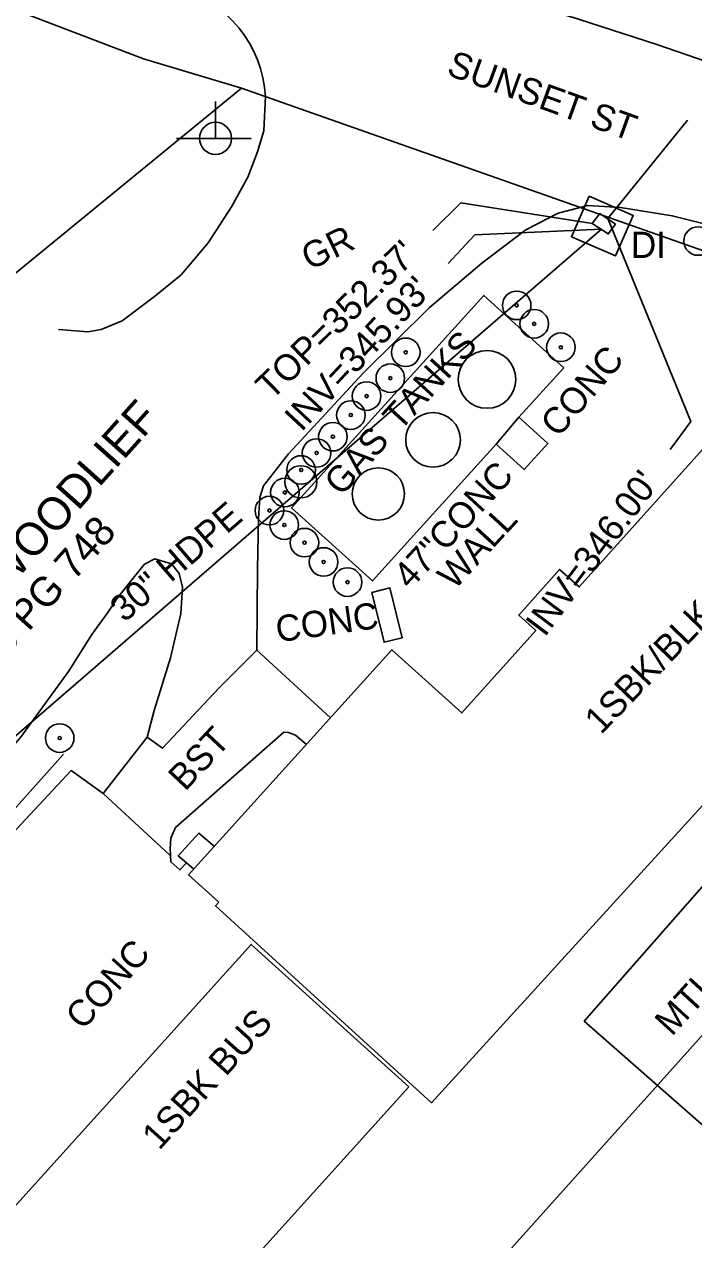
# Model space of a CAD drawing. Extents: x 2089016 to 2094354, y 862840 to 864725.
# Drawn here: x 2091878.1 to 2091980.3, y 864032.6 to 864218.1 of the extents above; entities that cross this region are included whole.
import ezdxf

# ---------------------------------------------------------------- set-up
doc = ezdxf.new("R2010")
doc.units = 0
for name, color, linetype in [('Exist Building', 7, 'Continuous'), ('Exist Building Metal Canopy', 7, 'Continuous'), ('Exist Building Metal Canopy Text', 7, 'Continuous'), ('Exist Building Text', 7, 'Continuous'), ('Exist Other Culture AG Tank', 7, 'Continuous'), ('Exist Other Culture AG Tank Text', 7, 'Continuous'), ('Exist Other Culture Area Outline', 7, 'Continuous'), ('Exist Other Culture Area Outline Text', 7, 'Continuous'), ('Exist Other Culture Fence Line', 7, 'Continuous'), ('Exist Other Culture Located Object CELL', 7, 'Continuous'), ('Exist Property Deed Book Text', 7, 'Continuous'), ('Exist Property Line', 7, 'Continuous'), ('Exist Property Owner Text', 7, 'Continuous'), ('Exist Right of Way Line', 7, 'Continuous'), ('Exist Roads Change in Surface', 7, 'Continuous'), ('Exist Roads EOP', 7, 'Continuous'), ('Exist Roads EOP Other', 7, 'Continuous'), ('Exist Roads EOP Other Text', 7, 'Continuous'), ('Exist Roads EOT', 7, 'Continuous'), ('Exist Roads Soil', 7, 'Continuous'), ('Exist Roads Soil Text', 7, 'Continuous'), ('Exist Structure Minor Drop Inlet', 7, 'Continuous'), ('Exist Structure Minor Drop Inlet Leader', 7, 'Continuous'), ('Exist Structure Minor Drop Inlet Text', 7, 'Continuous'), ('Exist Structure Minor Drop Inlet Top Elevation', 7, 'Continuous'), ('Exist Structure Minor Paved Ditch or Gutter', 7, 'Continuous'), ('Exist Structure Minor Pipes HDPE 30 Inch', 7, 'Continuous'), ('Exist Structure Minor Pipes HDPE 30 Inch Invert', 7, 'Continuous'), ('Exist Structure Minor Pipes HDPE 30 Inch Leader', 7, 'Continuous'), ('Exist Structure Minor Pipes HDPE 30 Inch Text', 7, 'Continuous'), ('Exist Structure Minor Pipes RCP 30 Inch', 7, 'Continuous'), ('Exist Structure Minor Pipes RCP 30 Inch Invert', 7, 'Continuous'), ('Exist Structure Minor Pipes RCP 30 Inch Leader', 7, 'Continuous'), ('Prop Drainage Structure Pipe RCP 30in Class IV Label', 7, 'Continuous'), ('Prop Drainage Structure Pipe RCP 36in Class IV', 7, 'Continuous'), ('Prop SS Fill Line', 7, 'Continuous'), ('R5707_NCDOT_FS_170814 - Exist Roads EOT', 7, 'Continuous')]:
    doc.layers.add(name, color=color, linetype=linetype)

msp = doc.modelspace()

# ---------------------------------------------------------------- linework, layer by layer
at = {"layer": 'Exist Building'}
msp.add_line((2091950.15, 864153.99), (2091953.61, 864158.12), dxfattribs=at)
msp.add_lwpolyline([(2091950.15, 864153.99), (2091931.26, 864133.13), (2091918.93, 864144.3), (2091948.29, 864176.71), (2091960.46, 864165.68), (2091953.61, 864158.12)], dxfattribs=at)
msp.add_lwpolyline([(2092025.57, 864147.09), (2091940.29, 864053.5), (2091907.31, 864083.55), (2091907.81, 864084.1), (2091903.21, 864088.27), (2091934.25, 864122.63), (2091944.9, 864112.99), (2091956.19, 864125.59), (2091953.59, 864127.93), (2091959.84, 864134.9), (2091962.84, 864132.21), (2091997.36, 864170.68), (2091998.21, 864171.63)], close=True, dxfattribs=at)
at = {"layer": 'Exist Building Metal Canopy'}
for points in [[(2092008.24, 864079.99), (2091981.86, 864049.93), (2091963.6, 864065.96), (2091989.97, 864096.01)], [(2091936.84, 864055.9), (2091875.11, 863987.57), (2091851.02, 864009.33), (2091912.76, 864077.66)]]:
    msp.add_lwpolyline(points, close=True, dxfattribs=at)
at = {"layer": 'Exist Other Culture AG Tank'}
for centre, radius in [((2091948.75, 864163.89), 4.41), ((2091940.51, 864154.66), 4.17), ((2091932.17, 864146.41), 3.99)]:
    msp.add_circle(centre, radius, dxfattribs=at)
at = {"layer": 'Exist Other Culture Area Outline'}
for points in [[(2091953.61, 864158.12), (2091958.01, 864154.13), (2091954.4, 864150.14), (2091950.15, 864153.99)], [(2091902.88, 864090.12), (2091901.6, 864091.2), (2091904.79, 864094.66), (2091907.14, 864092.62)]]:
    msp.add_lwpolyline(points, dxfattribs=at)
msp.add_lwpolyline([(2091931.15, 864131.39), (2091933.05, 864123.78), (2091935.82, 864124.47), (2091933.93, 864132.08)], close=True, dxfattribs=at)
at = {"layer": 'Exist Other Culture Fence Line'}
msp.add_line((2091857.39, 864076.87), (2091884.1, 864106.7), dxfattribs=at)
at = {"layer": 'Exist Other Culture Located Object CELL'}
for centre, radius in [((2091953.28, 864175.19), 2.18), ((2091953.28, 864175.19), 0.24), ((2091955.95, 864172.38), 2.18), ((2091955.95, 864172.38), 0.24), ((2091936.35, 864168.03), 2.18), ((2091960.02, 864168.8), 2.18), ((2091936.35, 864168.03), 0.24), ((2091960.02, 864168.8), 0.24), ((2091933.99, 864164.08), 2.18), ((2091933.99, 864164.08), 0.24), ((2091930.37, 864161.34), 2.18), ((2091927.97, 864158.45), 2.18), ((2091930.37, 864161.34), 0.24), ((2091927.97, 864158.45), 0.24), ((2091925.23, 864155.15), 2.18), ((2091922.74, 864152.66), 2.18), ((2091925.23, 864155.15), 0.24), ((2091922.74, 864152.66), 0.24), ((2091920.38, 864150.07), 2.18), ((2091920.38, 864150.07), 0.24), ((2091917.9, 864146.63), 2.18), ((2091915.55, 864143.88), 2.18), ((2091917.9, 864146.63), 0.24), ((2091915.55, 864143.88), 0.24), ((2091917.81, 864141.66), 2.18), ((2091917.81, 864141.66), 0.24), ((2091920.89, 864138.98), 2.18), ((2091920.89, 864138.98), 0.24), ((2091923.81, 864136.03), 2.18), ((2091923.81, 864136.03), 0.24), ((2091927.46, 864132.95), 2.18), ((2091927.46, 864132.95), 0.24), ((2091883.53, 864109.15), 2.18), ((2091883.53, 864109.15), 0.24)]:
    msp.add_circle(centre, radius, dxfattribs=at)
at = {"layer": 'Exist Property Line'}
msp.add_line((2091911.3, 864208.32), (2091739.6, 864068.07), dxfattribs=at)
at = {"layer": 'Exist Right of Way Line'}
for p, q in [((2091768.57, 864261.63), (2091896.32, 864212.8)), ((2091896.32, 864212.8), (2091911.3, 864208.32)), ((2091911.3, 864208.32), (2092063.24, 864154.88)), ((2092063.24, 864154.88), (2091854.39, 863921.86))]:
    msp.add_line(p, q, dxfattribs=at)
at = {"layer": 'Exist Roads Change in Surface'}
msp.add_line((2091890.18, 864100.7), (2091900.32, 864091.3), dxfattribs=at)
at = {"layer": 'Exist Roads EOP'}
msp.add_spline([(2091734.18, 863736.92), (2091737.57, 863740.74), (2091742.7, 863746.41), (2091746.39, 863749.99), (2091752.74, 863757.34), (2091779.15, 863786.15), (2091800.43, 863809.86), (2091817.14, 863828.66), (2091827.31, 863840.06), (2091854.93, 863870.83), (2091881.2, 863900.12), (2091888.17, 863907.69), (2091904.65, 863926.31), (2091929.6, 863954.75), (2091942.38, 863969.24), (2091969.89, 863999.82), (2091984.53, 864016.32), (2091999.97, 864033.43), (2092012.73, 864047.99), (2092025.65, 864062.7), (2092046.42, 864086.24), (2092066.29, 864109.17), (2092073.24, 864116), (2092075.7, 864118.27)], degree=3, dxfattribs=at)
at = {"layer": 'Exist Roads EOP Other'}
for points in [[(2091830.63, 863994.76), (2091827.43, 863997.96), (2091826.47, 864000.61), (2091825.69, 864006.48), (2091825.91, 864011.04), (2091828.35, 864018.06), (2091835.42, 864033.2), (2091847.32, 864055.21), (2091857.99, 864074.56), (2091869.16, 864086.97), (2091885.3, 864104.18), (2091890.18, 864100.7), (2091896.88, 864109.31), (2091899.21, 864107.63), (2091907.87, 864116.83), (2091913.63, 864122.58), (2091924.84, 864112.22)], [(2091921.18, 864108.17), (2091919.53, 864109.62), (2091918.47, 864110.01), (2091917.74, 864110.04), (2091901.22, 864095.48), (2091900.51, 864093.89), (2091900.38, 864092.28), (2091900.51, 864090.26), (2091901.87, 864089.03), (2091902.88, 864090.12), (2091904.01, 864089.16)]]:
    msp.add_lwpolyline(points, dxfattribs=at)
at = {"layer": 'Exist Roads EOT'}
msp.add_spline([(2091640.57, 863633.96), (2091642.21, 863635.11), (2091649.13, 863640.68), (2091667.19, 863659.41), (2091696.8, 863691.67), (2091725.32, 863721.95), (2091736.55, 863733.98), (2091755.7, 863754.61), (2091782.35, 863783.06), (2091806.22, 863808.81), (2091831.4, 863835.96), (2091859.62, 863866.77), (2091886.36, 863896.04), (2091909.82, 863922.03), (2091934.52, 863949.57), (2091947.55, 863964.17), (2091975.11, 863995.05), (2091990.59, 864012.13), (2092005.14, 864028.47), (2092018.17, 864043.09), (2092031.63, 864058.14), (2092052.57, 864081.55), (2092071.9, 864103.07)], degree=3, dxfattribs=at)
at = {"layer": 'Exist Roads Soil'}
msp.add_line((2091897.94, 864113.34), (2091896.88, 864109.31), dxfattribs=at)
for points in [[(2091932.99, 864228.49), (2091950.66, 864222.62), (2091962.74, 864218.85), (2091974.68, 864215.02), (2091986.8, 864210.83), (2091997.29, 864206.81), (2092009.63, 864202.38)], [(2091914.93, 864207.11), (2091914.69, 864201.83), (2091913.71, 864198.61), (2091912.27, 864194.76), (2091909.76, 864190.25), (2091906.21, 864184.74), (2091902.07, 864179.84), (2091897.99, 864176.52), (2091893.08, 864172.84), (2091889.86, 864171.49), (2091887.83, 864171.15), (2091883.35, 864171.53)], [(2091913.63, 864122.58), (2091913.74, 864134.95), (2091913.85, 864142.59), (2091914.08, 864145.89), (2091914.62, 864147.64), (2091918.44, 864152.53), (2091929.87, 864164.85), (2091939.94, 864174.81), (2091947.96, 864181.64), (2091954.7, 864186.73), (2091959.62, 864189.26), (2091964.12, 864190.41), (2091969.13, 864190.14), (2091977.03, 864188.86), (2091983.14, 864187.33), (2091989.07, 864185.08), (2091995.48, 864181.81)], [(2091861.47, 864090.93), (2091877.56, 864109.25), (2091884.9, 864119.3), (2091888.46, 864124.95), (2091890.88, 864128.32), (2091892.34, 864130.57), (2091894.77, 864133.57), (2091896.48, 864135.7), (2091898.07, 864136.49), (2091900.58, 864135.76), (2091901.79, 864134.29), (2091902.29, 864132.18), (2091902.02, 864128.16), (2091900.45, 864121.39), (2091897.94, 864113.34)]]:
    msp.add_lwpolyline(points, dxfattribs=at)
msp.add_arc((2091897.12, 864206.2), 17.83, 2.7401, 75.8362, dxfattribs=at)
at = {"layer": 'Exist Structure Minor Drop Inlet'}
msp.add_lwpolyline([(2091964.79, 864187.66), (2091967.25, 864186.09), (2091968.34, 864187.57), (2091965.96, 864189.21), (2091964.79, 864187.66)], dxfattribs=at)
at = {"layer": 'Exist Structure Minor Drop Inlet Leader'}
msp.add_lwpolyline([(2091964.79, 864187.66), (2091944.78, 864190.83), (2091940.49, 864186.64)], dxfattribs=at)
at = {"layer": 'Exist Structure Minor Paved Ditch or Gutter'}
msp.add_lwpolyline([(2091964.36, 864191.85), (2091971.07, 864188.93), (2091968.38, 864182.75), (2091961.67, 864185.67)], close=True, dxfattribs=at)
at = {"layer": 'Exist Structure Minor Pipes HDPE 30 Inch'}
msp.add_line((2091802.44, 864045.18), (2091966.23, 864186.8), dxfattribs=at)
at = {"layer": 'Exist Structure Minor Pipes HDPE 30 Inch Leader'}
msp.add_lwpolyline([(2091966.23, 864186.8), (2091946.89, 864185.95), (2091942.8, 864181.56)], dxfattribs=at)
at = {"layer": 'Exist Structure Minor Pipes RCP 30 Inch'}
msp.add_line((2091967.17, 864188.44), (2091979.34, 864203.45), dxfattribs=at)
at = {"layer": 'Exist Structure Minor Pipes RCP 30 Inch Leader'}
msp.add_lwpolyline([(2091967.17, 864188.44), (2091979.86, 864157.49), (2091976.68, 864153.21)], dxfattribs=at)
at = {"layer": 'Prop Drainage Structure Pipe RCP 30in Class IV Label'}
msp.add_circle((2091920.34, 864148.26), 2.46, dxfattribs=at)
at = {"layer": 'Prop Drainage Structure Pipe RCP 36in Class IV'}
msp.add_circle((2091980.97, 864185.01), 2.18, dxfattribs=at)
at = {"layer": 'Prop SS Fill Line'}
msp.add_line((2091907.32, 864200.68), (2091907.32, 864200.68), dxfattribs=at)
msp.add_lwpolyline([(2091901.38, 864200.68), (2091912.72, 864200.64), (2091907.32, 864200.66), (2091907.32, 864206.3)], dxfattribs=at)
msp.add_circle((2091907.32, 864200.68), 2.45, dxfattribs=at)
at = {"layer": 'R5707_NCDOT_FS_170814 - Exist Roads EOT'}
msp.add_spline([(2091640.57, 863633.96), (2091642.21, 863635.11), (2091649.13, 863640.68), (2091667.19, 863659.41), (2091696.8, 863691.67), (2091725.32, 863721.95), (2091736.55, 863733.98), (2091755.7, 863754.61), (2091782.35, 863783.06), (2091806.22, 863808.81), (2091831.4, 863835.96), (2091859.62, 863866.77), (2091886.36, 863896.04), (2091909.82, 863922.03), (2091934.52, 863949.57), (2091947.55, 863964.17), (2091975.11, 863995.05), (2091990.59, 864012.13), (2092005.14, 864028.47), (2092018.17, 864043.09), (2092031.63, 864058.14), (2092052.57, 864081.55), (2092071.9, 864103.07)], degree=3, dxfattribs=at)

# ---------------------------------------------------------------- texts
at = {"layer": 'Exist Building Metal Canopy Text'}
for s, rotation, p in [('MTL CAN', 47.5793, (2091976.96, 864063.51)), ('1SBK BUS', 47.9663, (2091898.73, 864046.12))]:
    msp.add_text(s, height=4, rotation=rotation, dxfattribs=at).set_placement(p)
at = {"layer": 'Exist Building Text'}
for s, rotation, p in [('47"CONC ', 47.3689, (2091937.05, 864131.69)), ('WALL', 47.3689, (2091943.78, 864131.62)), ('1SBK/BLK BUS', 46.0965, (2091966.16, 864109.58))]:
    msp.add_text(s, height=4, rotation=rotation, dxfattribs=at).set_placement(p)
at = {"layer": 'Exist Other Culture AG Tank Text'}
for s, rotation, p in [('TANKS', 47.5051, (2091935.45, 864155.84)), ('GAS ', 48.808, (2091926.57, 864145.92))]:
    msp.add_text(s, height=4, rotation=rotation, dxfattribs=at).set_placement(p)
at = {"layer": 'Exist Other Culture Area Outline Text'}
for rotation, p in [(49.4141, (2091959.63, 864154.87)), (8.1345, (2091916.8, 864123.75))]:
    msp.add_text('CONC ', height=4, rotation=rotation, dxfattribs=at).set_placement(p)
at = {"layer": 'Exist Property Deed Book Text'}
msp.add_text('DB 695 PG 748', height=4.5, rotation=48.1706, dxfattribs=at).set_placement((2091864.28, 864109.09))
at = {"layer": 'Exist Property Owner Text'}
msp.add_text('ADLAI S WOODLIEF', height=5, rotation=48.1706, dxfattribs=at).set_placement((2091856.83, 864110.77))
at = {"layer": 'Exist Roads EOP Other Text'}
for s, rotation, p in [(' BST', 46.8763, (2091901.66, 864099.82)), ('CONC', 48.0217, (2091887.05, 864064.42))]:
    msp.add_text(s, height=4, rotation=rotation, dxfattribs=at).set_placement(p)
at = {"layer": 'Exist Roads Soil Text'}
for s, rotation, p in [('SUNSET ST', 340.1457, (2091942.42, 864210.42)), ('GR', 25.755, (2091921.67, 864180.47))]:
    msp.add_text(s, height=4, rotation=rotation, dxfattribs=at).set_placement(p)
at = {"layer": 'Exist Structure Minor Drop Inlet Text'}
msp.add_text('DI', height=4, dxfattribs=at).set_placement((2091970.72, 864182.43))
at = {"layer": 'Exist Structure Minor Drop Inlet Top Elevation'}
msp.add_text("TOP=352.37'", height=4, rotation=44.3053, dxfattribs=at).set_placement((2091915.86, 864160.59))
at = {"layer": 'Exist Structure Minor Pipes HDPE 30 Inch Invert'}
msp.add_text("INV=345.93'", height=4, rotation=46.9987, dxfattribs=at).set_placement((2091920.43, 864155.76))
at = {"layer": 'Exist Structure Minor Pipes HDPE 30 Inch Text'}
msp.add_text('30" HDPE', height=4, rotation=40.8474, dxfattribs=at).set_placement((2091893.41, 864126.68))
at = {"layer": 'Exist Structure Minor Pipes RCP 30 Inch Invert'}
msp.add_text("INV=346.00'", height=4, rotation=53.2282, dxfattribs=at).set_placement((2091957.56, 864124.44))

doc.saveas('drawing.dxf')
